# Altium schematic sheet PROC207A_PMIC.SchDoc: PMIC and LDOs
size 431 x 279 mm; Date: Not shown in title block; ApprovedBy: Not shown in title block; CheckedBy: Not shown in title block; Author: Not shown in title block; CompanyName: Not shown in title block; DrawnBy: Mistral; Engineer: Not shown in title block; Organization: Not shown in title block; Address1: Not shown in title block; Address2: Not shown in title block; Address3: Not shown in title block; Address4: Not shown in title block; DocumentNumber: 16; Revision: Use project parameter SCH_Rev; SheetNumber: 5; SheetTotal: 18; PageSetup: Record=PageOptions¦CenterHorizontal=True¦CenterVertical=True¦PrintScale=1.00¦XCorrection=1.00¦YCorrection=1.00¦PrintKind=0¦BorderSize=5000000¦LeftOffset=0¦BottomOffset=0¦Orientation=2¦PaperLength=1000¦PaperWidth=1000¦Scale=100¦PaperSource=15¦PrintQuality=600¦MediaType=1¦DitherType=10¦PaperKind=Letter¦PrintScaleMode=1
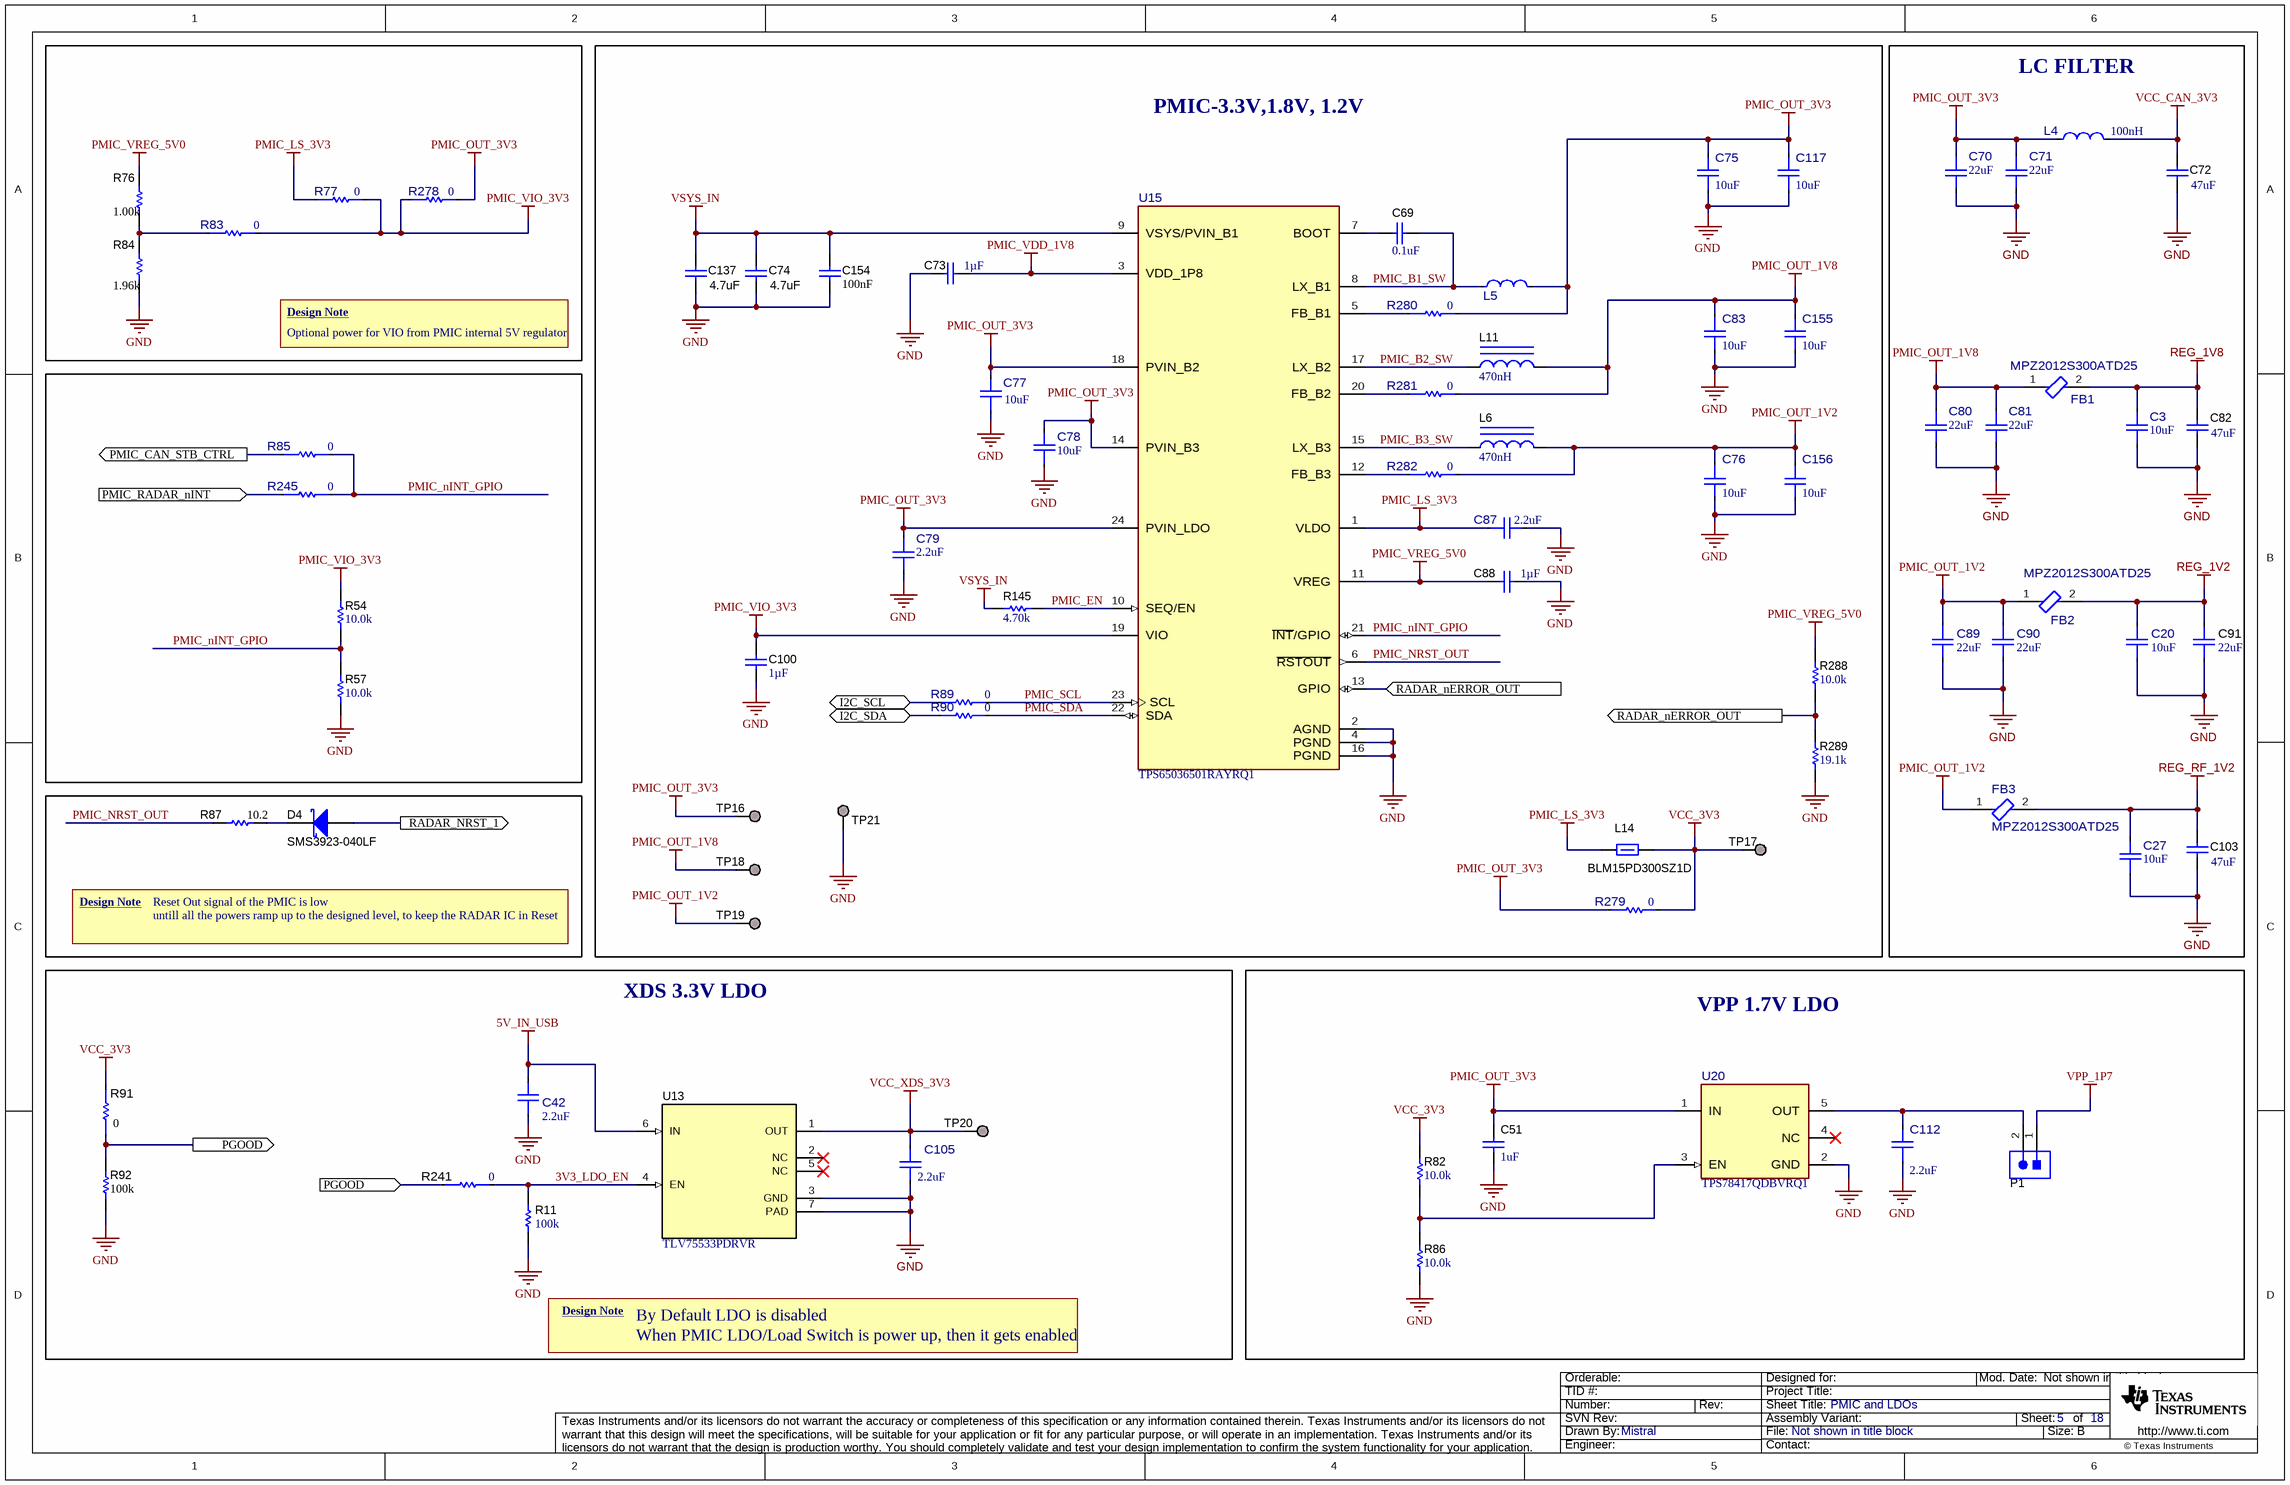
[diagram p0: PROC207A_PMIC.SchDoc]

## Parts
C3  ValueDisplayed: 10uF  [FP-CGA4J3X7S1A106K125AE_0805-MFG]  (hidden comment: CGA4J3X7S1A106K125AE)
C20  ValueDisplayed: 10uF  [FP-CGA4J3X7S1A106K125AE_0805-MFG]  (hidden comment: CGA4J3X7S1A106K125AE)
C27  ValueDisplayed: 10uF  [FP-CGA4J3X7S1A106K125AE_0805-MFG]  (hidden comment: CGA4J3X7S1A106K125AE)
C42  ValueDisplayed: 2.2uF  [FP-GRT155C71A225KE13D_0402-MFG]  (hidden comment: GRT155C71A225KE13D)
C51  ValueDisplayed: 1uF  [0402_070]  (hidden comment: GCM155C71A105KE38D)
C69  ValueDisplayed: 0.1uF  [0402]  (hidden comment: GCM155R71H104KE02D)
C70  ValueDisplayed: 22uF  [FP-GRM31CR70J226ME19K_1206-MFG]  (hidden comment: GRM31CR70J226ME19K)
C71  ValueDisplayed: 22uF  [FP-GRM31CR70J226ME19K_1206-MFG]  (hidden comment: GRM31CR70J226ME19K)
C72  ValueDisplayed: 47uF  [1206_180]  (hidden comment: GRM31CR60J476ME19L)
C73  Cap_F: 1µF  [0603]  (hidden comment: CL10B105KA8NNNC)
C74  ValueDisplayed: 4.7uF  [1206_180L]  (hidden comment: C3216X7R1H475K160AC)
C75  ValueDisplayed: 10uF  [FP-CGA4J3X7S1A106K125AE_0805-MFG]  (hidden comment: CGA4J3X7S1A106K125AE)
C76  ValueDisplayed: 10uF  [FP-CGA4J3X7S1A106K125AE_0805-MFG]  (hidden comment: CGA4J3X7S1A106K125AE)
C77  ValueDisplayed: 10uF  [FP-CGA4J3X7S1A106K125AE_0805-MFG]  (hidden comment: CGA4J3X7S1A106K125AE)
C78  ValueDisplayed: 10uF  [FP-CGA4J3X7S1A106K125AE_0805-MFG]  (hidden comment: CGA4J3X7S1A106K125AE)
C79  ValueDisplayed: 2.2uF  [FP-GRT155C71A225KE13D_0402-MFG]  (hidden comment: GRT155C71A225KE13D)
C80  ValueDisplayed: 22uF  [FP-GRM31CR70J226ME19K_1206-MFG]  (hidden comment: GRM31CR70J226ME19K)
C81  ValueDisplayed: 22uF  [FP-GRM31CR70J226ME19K_1206-MFG]  (hidden comment: GRM31CR70J226ME19K)
C82  ValueDisplayed: 47uF  [1206_180]  (hidden comment: GRM31CR60J476ME19L)
C83  ValueDisplayed: 10uF  [FP-CGA4J3X7S1A106K125AE_0805-MFG]  (hidden comment: CGA4J3X7S1A106K125AE)
C87  ValueDisplayed: 2.2uF  [FP-GRT155C71A225KE13D_0402-MFG]  (hidden comment: GRT155C71A225KE13D)
C88  Cap_F: 1µF  [0603]  (hidden comment: CL10B105KA8NNNC)
C89  ValueDisplayed: 22uF  [FP-GRM31CR70J226ME19K_1206-MFG]  (hidden comment: GRM31CR70J226ME19K)
C90  ValueDisplayed: 22uF  [FP-GRM31CR70J226ME19K_1206-MFG]  (hidden comment: GRM31CR70J226ME19K)
C91  ValueDisplayed: 22uF  [FP-GRM31CR70J226ME19K_1206-MFG]  (hidden comment: GRM31CR70J226ME19K)
C100  Cap_F: 1µF  [0603]  (hidden comment: CL10B105KA8NNNC)
C103  ValueDisplayed: 47uF  [1206_180]  (hidden comment: GRM31CR60J476ME19L)
C105  ValueDisplayed: 2.2uF  [FP-GRT155C71A225KE13D_0402-MFG]  (hidden comment: GRT155C71A225KE13D)
C112  ValueDisplayed: 2.2uF  [FP-GRT155C71A225KE13D_0402-MFG]  (hidden comment: GRT155C71A225KE13D)
C117  ValueDisplayed: 10uF  [FP-CGA4J3X7S1A106K125AE_0805-MFG]  (hidden comment: CGA4J3X7S1A106K125AE)
C137  ValueDisplayed: 4.7uF  [1206_180L]  (hidden comment: C3216X7R1H475K160AC)
C154  Cap_F: 100nF  [0402]  (hidden comment: GCM155R71H104KE02D)
C155  ValueDisplayed: 10uF  [FP-CGA4J3X7S1A106K125AE_0805-MFG]  (hidden comment: CGA4J3X7S1A106K125AE)
C156  ValueDisplayed: 10uF  [FP-CGA4J3X7S1A106K125AE_0805-MFG]  (hidden comment: CGA4J3X7S1A106K125AE)
D4  SMS3923-040LF  [SOD-882]
FB1  MPZ2012S300ATD25  [FP-MPZ2012S300ATD25_0805-MFG]
FB2  MPZ2012S300ATD25  [FP-MPZ2012S300ATD25_0805-MFG]
FB3  MPZ2012S300ATD25  [FP-MPZ2012S300ATD25_0805-MFG]
L4  Ind_H: 100nH  [FP-LQM2MPZR10MJHL_0806 (2016)-MFG]  (hidden comment: LQM2MPZR10MJHL)
L5  TFM252012ALVA1R5MTAA  [FP-TFM252012ALVA1R5MTAA_1008-MFG]  (value not drawn)
L6  ValueDisplayed: 470nH  [TFM201610ALMA]  (hidden comment: TFM201610ALMAR47MTAA)
L11  ValueDisplayed: 470nH  [TFM201610ALMA]  (hidden comment: TFM201610ALMAR47MTAA)
L14  BLM15PD300SZ1D  [0402L]
P1  TSW-102-07-G-S  [TSW-102-07-G-S]  (value not drawn)
R11  ValueDisplayed: 100k  [0402]  (hidden comment: CRCW0402100KFKED)
R54  ValueDisplayed: 10.0k  [0402L]  (hidden comment: CRCW040210K0FKED)
R57  ValueDisplayed: 10.0k  [0402L]  (hidden comment: CRCW040210K0FKED)
R76  ValueDisplayed: 1.00k  [0402]  (hidden comment: ERJ-2RKF1001X)
R77  value 0  [FP-ERJ-2GE0R00X_0402-MFG]  (hidden comment: ERJ-2GE0R00X)
R82  ValueDisplayed: 10.0k  [0402L]  (hidden comment: CRCW040210K0FKED)
R83  value 0  [FP-ERJ-2GE0R00X_0402-MFG]  (hidden comment: ERJ-2GE0R00X)
R84  ValueDisplayed: 1.96k  [0402]  (hidden comment: CRCW04021K96FKED)
R85  value 0  [FP-ERJ-2GE0R00X_0402-MFG]  (hidden comment: ERJ-2GE0R00X)
R86  ValueDisplayed: 10.0k  [0402L]  (hidden comment: CRCW040210K0FKED)
R87  ValueDisplayed: 10.2  [0402]  (hidden comment: CRCW040210R2FKED)
R89  value 0  [FP-ERJ-2GE0R00X_0402-MFG]  (hidden comment: ERJ-2GE0R00X)
R90  value 0  [FP-ERJ-2GE0R00X_0402-MFG]  (hidden comment: ERJ-2GE0R00X)
R91  value 0  [FP-ERJ-2GE0R00X_0402-MFG]  (hidden comment: ERJ-2GE0R00X)
R92  ValueDisplayed: 100k  [0402]  (hidden comment: CRCW0402100KFKED)
R145  value 4.70k  [0402]  (hidden comment: RC0402FR-074K7L)
R241  value 0  [FP-ERJ-2GE0R00X_0402-MFG]  (hidden comment: ERJ-2GE0R00X)
R245  value 0  [FP-ERJ-2GE0R00X_0402-MFG]  (hidden comment: ERJ-2GE0R00X)
R278  value 0  [FP-ERJ-2GE0R00X_0402-MFG]  (hidden comment: ERJ-2GE0R00X)
R279  value 0  [FP-ERJ-2GE0R00X_0402-MFG]  (hidden comment: ERJ-2GE0R00X)
R280  value 0  [FP-ERJ-2GE0R00X_0402-MFG]  (hidden comment: ERJ-2GE0R00X)
R281  value 0  [FP-ERJ-2GE0R00X_0402-MFG]  (hidden comment: ERJ-2GE0R00X)
R282  value 0  [FP-ERJ-2GE0R00X_0402-MFG]  (hidden comment: ERJ-2GE0R00X)
R288  ValueDisplayed: 10.0k  [0402L]  (hidden comment: CRCW040210K0FKED)
R289  ValueDisplayed: 19.1k  [0402]  (hidden comment: CRCW040219K1FKED)
TP16  TESTPOINT  [TP_25MIL-SMT]  (value not drawn)  (no BOM)
TP17  TESTPOINT  [TP_25MIL-SMT]  (value not drawn)  (no BOM)
TP18  TESTPOINT  [TP_25MIL-SMT]  (value not drawn)  (no BOM)
TP19  TESTPOINT  [TP_25MIL-SMT]  (value not drawn)  (no BOM)
TP20  TESTPOINT  [TP_25MIL-SMT]  (value not drawn)  (no BOM)
TP21  TESTPOINT  [TP_VIA_060RND040]  (value not drawn)  (no BOM)
U13  TLV75533PDRVR  [DRV0006A]
U15  TPS65036501RAYRQ1  [RAY0024B-MFG]
U20  TPS78417QDBVRQ1  [DBV0005A-MFG]

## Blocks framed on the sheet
PMIC-3.3V,1.8V, 1.2V: C69 C73-C79 C83 C87 C88 C100 C117 C137 C154-C156 L5 L6 L11 L14 R89 R90 R145 R279-R282 R288 R289 TP16-TP19 TP21 U15
LC FILTER: C3 C20 C27 C70-C72 C80-C82 C89-C91 C103 FB1-FB3 L4
VPP 1.7V LDO: C51 C112 P1 R82 R86 U20

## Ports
I2C_SCL (bidir), I2C_SDA (bidir), PGOOD (in), PGOOD (out), PMIC_CAN_STB_CTRL (out), PMIC_RADAR_nINT (in), RADAR_nERROR_OUT (in), RADAR_nERROR_OUT (out), RADAR_NRST_1 (out)

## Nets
5V_IN_USB: C42.2 U13.6(IN)
GND: C3.1 C20.1 C27.1 C42.1 C51.2 C70.2 C71.2 C72.1 C73.2 C74.2 C75.1 C76.2 C77.1 C78.1 C79.2 C80.2 C81.2 C82.1 C83.2 C87.2 C88.1 C89.2 C90.2 C91.1 C100.2 C103.1 C105.2 C112.1 C117.1 C137.2 C154.1 C155.1 C156.1 R11.1 R57.1 R84.1 R86.1 R92.1 R289.1 TP21.1 U13.3(GND) U13.7(PAD) U15.2(AGND) U15.4(PGND) U15.16(PGND) U20.2(GND)
PMIC_LS_3V3: C87.1 L14.1 R77.1 U15.1(VLDO)
PMIC_OUT_1V2: C76.1 C89.1 C90.1 C156.2 FB2.1 FB3.1 L6.2 R282.2 TP19.1
PMIC_OUT_1V8: C80.1 C81.1 C83.1 C155.2 FB1.1 L11.2 R281.2 TP18.1
PMIC_OUT_3V3: C51.1 C70.1 C71.1 C75.2 C77.2 C78.2 C79.1 C117.2 L4.1 L5.2 R278.2 R279.1 R280.2 TP16.1 U15.14(PVIN_B3) U15.18(PVIN_B2) U15.24(PVIN_LDO) U20.1(IN)
PMIC_VDD_1V8: C73.1 U15.3(VDD_1P8)
PMIC_VIO_3V3: C100.1 R54.2 R77.2 R83.2 R278.1 U15.19(VIO)
PMIC_VREG_5V0: C88.2 R76.1 R288.2 U15.11(VREG)
REG_1V2: C20.2 C91.2 FB2.2
REG_1V8: C3.2 C82.2 FB1.2
REG_RF_1V2: C27.2 C103.2 FB3.2
VCC_3V3: L14.2 R82.2 R91.2 R279.2 TP17.1
VCC_CAN_3V3: C72.2 L4.2
VCC_XDS_3V3: C105.1 TP20.1 U13.1(OUT)
VPP_1P7: P1.1
VSYS_IN: C74.1 C137.1 C154.2 R145.2 U15.9(VSYS/PVIN_B1)
3V3_LDO_EN: R11.2 R241.2 U13.4(EN)
I2C_SCL: R89.1 ; port I2C_SCL
I2C_SDA: R90.1 ; port I2C_SDA
PGOOD: R91.1 R92.2 R241.1 ; port PGOOD
PMIC_B1_SW: C69.2 L5.1 U15.8(LX_B1)
PMIC_B2_SW: L11.1 U15.17(LX_B2)
PMIC_B3_SW: L6.1 U15.15(LX_B3)
PMIC_CAN_STB_CTRL: R85.1 ; port PMIC_CAN_STB_CTRL
PMIC_EN: R145.1 U15.10(SEQ/EN)
PMIC_nINT_GPIO: R54.1 R57.2 R85.2 R245.2 U15.21(~{INT}/GPIO)
PMIC_NRST_OUT: R87.1 U15.6(~{RSTOUT})
PMIC_RADAR_nINT: R245.1 ; port PMIC_RADAR_nINT
PMIC_SCL: R89.2 U15.23(SCL)
PMIC_SDA: R90.2 U15.22(SDA)
RADAR_nERROR_OUT: R288.1 R289.2 U15.13(GPIO) ; port RADAR_nERROR_OUT
RADAR_NRST_1: D4.2(A) ; port RADAR_NRST_1
NetC69_1: C69.1 U15.7(BOOT)
NetC112_2: C112.2 P1.2 U20.5(OUT)
NetD4_1: D4.1(K) R87.2
NetR76_2: R76.2 R83.1 R84.2
NetR82_1: R82.1 R86.2 U20.3(EN)
NetR280_1: R280.1 U15.5(FB_B1)
NetR281_1: R281.1 U15.20(FB_B2)
NetR282_1: R282.1 U15.12(FB_B3)

Not connected (* = marked no-connect by the designer): U13 2(NC)* 5(NC)*; U20 4(NC)*

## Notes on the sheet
- Design Note
- Optional power for VIO from PMIC internal 5V regulator
- Reset Out signal of the PMIC is low
- untill all the powers ramp up to the designed level, to keep the RADAR IC in Reset
- XDS 3.3V LDO
- By Default LDO is disabled
- When PMIC LDO/Load Switch is power up, then it gets enabled

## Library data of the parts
C3 C20 C27 C75-C78 C83 C117 C155 C156 = CMP-0089543-1: 10µF ±10% 10V Ceramic Capacitor X7S 0805 (2012 Metric); Manufacturer: TDK; TempCo: 22%; SizeZ_mm: 1.5mm; AEC Qualified: Yes; AEC Grade: Grade 1
C42 C79 C87 C105 = CMP-0094968-1: Multi-Layer Ceramic Capacitor 2.2uF 10V X7S ±10% 0402 Paper T/R; Manufacturer: Murata; TempCo: 22%; Value: 2.2µF; SizeZ_mm: 0.7mm; AEC Qualified: Yes; AEC Grade: Grade 1
C51 = CMP-0006349-2: CAP, CERM, 1 uF, 10 V, +/- 10%, X7S, AEC-Q200 Grade 1, 0402; Manufacturer: MuRata; Polarized: N; Value: 1uF; U/M: EA; Cap_F: 1µF; Value1: Unknown; VDC_V: 10V; TaMin_C: -55°C; TaMax_C: 125°C; Cap_Case: 0402; SizeArea_mm2: 0.5; SizeAreaWB_mm2: 3; SizeX_mm: 1; SizeZ_mm: 0.7; AEC Category: Q200; AEC Qualified: Y
C69 = CMP-0006356-2: CAP, CERM, 0.1 uF, 50 V, +/- 10%, X7R, AEC-Q200 Grade 1, 0402; Manufacturer: MuRata; TaMin_C: -55°C; Polarized: N; SizeAreaWB_mm2: 3; Value1: Unknown; U/M: EA; Value: 0.1uF; TaMax_C: 125°C; SizeZ_mm: 0.6; SizeX_mm: 1; SizeY_mm: 0.5; Value2: 50V; AEC Qualified: Y; Cap_F: 100nF; AEC Category: Q200
C70 C71 C80 C81 C89 C90 = CMP-0092150-1: Chip Multilayer Ceramic Capacitors for General Purpose, 1206, 22uF, X7R, 15%, 20%, 6.3V; Manufacturer: Murata; Value: 22µF; SizeZ_mm: 1.8mm; AEC Qualified: No
C72 C82 C103 = CMP-0008940-2: CAP, CERM, 47 uF, 6.3 V, +/- 20%, X5R, 1206; Manufacturer: MuRata; TaMin_C: -55°C; ESR_ohm: 3m; Polarized: N; SizeAreaWB_mm2: 10.92; Value1: 0.003 ohm; U/M: EA; Value: 47uF; TaMax_C: 85°C; SizeZ_mm: 1.8; SizeX_mm: 3.2; SizeY_mm: 1.6; Cap_Case: 1206; Value2: 6.3V; SizeArea_mm2: 5.12; Cap_F: 47µF; AEC Category: Q200
C73 C88 C100 = CMP-0086540-3: CAP, 1uF, 25V, ±10%, X7R, 0603; Manufacturer: Samsung; TempCo: 15%; SizeZ_mm: 0.9mm; AEC Qualified: No; Symbol Name: SYM-CL10B105KA8NNNC
C74 C137 = CMP-0008702-2: CAP, CERM, 4.7 uF, 50 V, +/- 10%, X7R, 1206; Manufacturer: TDK; TaMin_C: -55°C; ESR_ohm: 3.158m; Polarized: N; SizeAreaWB_mm2: 10.92; Value1: 0.003158 ohm; U/M: EA; Value: 4.7uF; TaMax_C: 125°C; SizeZ_mm: 1.8; SizeX_mm: 3.2; SizeY_mm: 1.6; Cap_Case: 1206_180; Value2: 50V; SizeArea_mm2: 5.12; Cap_F: 4.7µF; IRMS_A: 4.08379A; AEC Category: Q200
C91 = CMP-0092150-1: Chip Multilayer Ceramic Capacitors for General Purpose, 1206, 22uF, X7R, 15%, 20%, 6.3V; Manufacturer: Murata; SizeZ_mm: 1.8mm; AEC Qualified: No; Value: 22µF
C112 = CMP-0094968-1: Multi-Layer Ceramic Capacitor 2.2uF 10V X7S ±10% 0402 Paper T/R; Manufacturer: Murata; AEC Grade: Grade 1; Cap_F: 2.2µF; SizeZ_mm: 0.7mm; Value: 2.2µF; AEC Qualified: Yes; TempCo: 22%
C154 = CMP-0006356-2: CAP, CERM, 0.1 uF, 50 V, +/- 10%, X7R, AEC-Q200 Grade 1, 0402; Manufacturer: MuRata; AEC Qualified: Y; SizeZ_mm: 0.6; VDC_V: 50V; AEC Category: Q200; AEC Grade: 1; Polarized: N; SizeArea_mm2: 0.5; SizeAreaWB_mm2: 3; TaMax_C: 125°C; TaMin_C: -55°C; U/M: EA; Value1: Unknown; Value: 0.1uF
D4 = CMP-0078187-3: Diode, Schottky,  V, 0.01 A, SOD-882; Manufacturer: Skyworks Solutions; SizeArea_mm2: 0.6; SizeAreaWB_mm2: 3.2; Io_A: 10mA; SizeX_mm: 1; Value1: 0.01A; SizeZ_mm: 0.5; Value2: 0.34V; AEC Category: Q101; Vf_V: 340mV; TJmax_C: 150°C; AEC Qualified: N
FB1-FB3 = CMP-0091544-1: 30 Ohms @ 100MHz 1 Power Line Ferrite Bead 0805 (2012 Metric) 6A 10mOhm; Manufacturer: TDK; AEC Grade: Grade 1; Impedance At Frequency: 30Ω @ 100MHz; SizeZ_mm: 1.05mm; DCR_ohm: 10m; AEC Qualified: Yes
L4 = CMP-0095018-1: 100nH Shielded Multilayer Inductor 4A 19mOhm Max 0806 (2016 Metric); Manufacturer: Murata; Tolerance_%: 20%; Self Resonant Frequency: 200MHz; Test Frequency: 1MHz; Irms: 4000mA; Shrouded: true; SizeZ_mm: 1.2mm; Value: 0.1uH; AEC Grade: Grade 1; DCR_ohm: 0.019; Material: Ferrite; AEC Qualified: Yes
L5 = CMP-0121156-1: 1.5 µH Shielded Thin Film Inductor 3.1 A 60mOhm Max 1008 (2520 Metric); Manufacturer: TDK; AEC Grade: Grade 0; AEC Qualified: Yes; DCR_ohm: 60m; Ind_H: 1.5µH; Irms: 3.3A; Material: Metal; SizeZ_mm: 1.2mm; Value: 1.5uH; Shrouded: true; Test Frequency: 1MHz; Tolerance_%: 20%
L6 L11 = CMP-0081095-1: Inductor, Shielded, Metal Composite, 470 nH, 3.9 A, 0.039 ohm, AEC-Q200 Grade 0, SMD; Manufacturer: TDK; Isat: 4.5A @ 30% inductance drop; Irms: 3.9A @ 40C rise; SizeAreaWB_mm2: 7.8; DCR_ohm: 39m; Value: 470nH; Imax_A: 3.9A; SizeZ_mm: 1; SizeX_mm: 2; SizeY_mm: 1.6; SizeArea_mm2: 3.2; AEC Qualified: Y; AEC Grade: 0; AEC Category: Q200
L14 = CMP-0078934-1: Inductor, Ferrite Bead, Ferrite, 2.2 A, 0.035 ohm, AEC-Q200 Grade 1, SMD; Manufacturer: MuRata; AEC Category: Q200; AEC Grade: 1; AEC Qualified: Y; DCR_ohm: 0.035; Imax_A: 2.2A; SizeArea_mm2: 0.5; SizeAreaWB_mm2: 3; SizeZ_mm: 0.6
P1 = CMP-0075405-3: Header, 100mil, 2x1, Gold, TH; Manufacturer: Samtec; Pitch_mm: 2.54; Cert_VDE: N; Gender: Male; Cert_CSA: Y; Voltage_V: 550V; Green_REACh: Passed; Current_A: 6.3A; Green_Lifecycle: Active; Row_Count: 1
R11 R92 = CMP-0025950-3: RES, 100 k, 1%, 0.063 W, AEC-Q200 Grade 0, 0402; Manufacturer: Vishay-Dale; Power_W: 63mW; TempCo: 100 ppm/C; Value: 100k; EIA_Code: E96; SizeX_mm: 1; SizeY_mm: 0.5; SizeZ_mm: 0.6; Value2: 0.063W; AEC Qualified: Y; VDC_V: 50V; AEC Category: Q200; AEC Grade: 0
R54 R57 R82 R86 R288 = CMP-0025958-3: RES, 10.0 k, 1%, 0.063 W, AEC-Q200 Grade 0, 0402; Manufacturer: Vishay-Dale; Power_W: 63mW; TempCo: 100 ppm/C; Value_Code: 10k0; Value: 10.0k; EIA_Code: E96; Res_ohm: 10k; SizeX_mm: 1; SizeY_mm: 0.5; SizeZ_mm: 0.6; Value2: 0.063W; AEC Qualified: Y; VDC_V: 50V; AEC Category: Q200; AEC Grade: 0
R76 = CMP-0026657-1: RES, 1.00 k, 1%, 0.1 W, 0402; Manufacturer: Panasonic; Power_W: 100mW; TempCo: 100 ppm/C; Value_Code: 1k00; U/M: EA; Value: 1.00k; EIA_Code: E96; Res_ohm: 1k; SizeX_mm: 1; SizeY_mm: 0.5; SizeZ_mm: 0.6; Value2: 0.1W; VDC_V: 50V; AEC Category: Q200
R77 R83 R278-R282 = CMP-0002710-1: 0 Ohms Jumper Chip Resistor 0402 (1005 Metric) Automotive AEC-Q200 Thick Film; Manufacturer: Panasonic; AEC Grade: Grade 0; AEC Qualified: Yes; SizeZ_mm: 0.4mm; Power: 100mW
R84 = CMP-0026099-2: RES, 1.96 k, 1%, 0.063 W, AEC-Q200 Grade 0, 0402; Manufacturer: Vishay-Dale; Power_W: 63mW; TempCo: 100 ppm/C; Value_Code: 1k96; Value: 1.96k; EIA_Code: E96; SizeX_mm: 1; SizeY_mm: 0.5; SizeZ_mm: 0.6; Value2: 0.063W; AEC Qualified: Y; VDC_V: 50V; AEC Category: Q200; AEC Grade: 0
R85 R89-R91 R241 R245 = CMP-0002710-1: 0 Ohms Jumper Chip Resistor 0402 (1005 Metric) Automotive AEC-Q200 Thick Film; Manufacturer: Panasonic; SizeZ_mm: 0.4mm; AEC Qualified: Yes; AEC Grade: Grade 0; Power: 100mW
R87 = CMP-0025964-3: RES, 10.2, 1%, 0.063 W, AEC-Q200 Grade 0, 0402; Manufacturer: Vishay-Dale; Power_W: 63mW; TempCo: 100 ppm/C; Value_Code: 10R2; Value: 10.2; EIA_Code: E96; SizeX_mm: 1; SizeY_mm: 0.5; SizeZ_mm: 0.6; Value2: 0.063W; AEC Qualified: Y; VDC_V: 50V; AEC Category: Q200; AEC Grade: 0
R145 = CMP-0026739-1: RES, 4.70 k, 1%, 0.0625 W, 0402; Manufacturer: Yageo America; VDC_V: 50V; AEC Qualified: N; SizeZ_mm: 0.6; TempCo: 100 ppm/C; AEC Category: Q200; Power_W: 62.5mW; Res_ohm: 4.7k; SizeArea_mm2: 0.5; SizeX_mm: 1; U/M: EA; Value_Code: 4k70
R289 = CMP-0026067-3: RES, 19.1 k, 1%, 0.063 W, AEC-Q200 Grade 0, 0402; Manufacturer: Vishay-Dale; Power_W: 63mW; TempCo: 100 ppm/C; Value_Code: 19k1; Value: 19.1k; EIA_Code: E96; SizeX_mm: 1; SizeY_mm: 0.5; SizeZ_mm: 0.6; Value2: 0.063W; AEC Qualified: Y; VDC_V: 50V; AEC Category: Q200; AEC Grade: 0
TP16-TP21 = CMP-0078143-3: TEST POINT.  No entry in BOM.
U13 = CMP-0013427-7: 500mA LDO, DRV0006A (WSON-6); Manufacturer: Texas Instruments; SizeX_mm: 2; CompType: IC; SizeZ_mm: 0.8; SizeArea_mm2: 4; SizeAreaWB_mm2: 9; U/M: EA
U15 = CMP-0123008-1: Automotive Camera, Radar and MCU PMIC; Manufacturer: Texas Instruments; SizeZ_mm: 1mm; AEC Qualified: No; Max Supply Voltage: 35V; Min Supply Voltage: 4V; Number Of Outputs: 4; Output Voltage: 3-5.5V; Standoff Height: 0mm; TaMax_C: +125°C; TaMin_C: -40°C
U20 = CMP-0092338-1: Linear Voltage Regulator IC Positive Fixed Output 300mA SOT-23-5; Manufacturer: Texas Instruments; TaMin_C: -40°C; Output Voltage: 1.7V; Standoff Height: 0mm; SizeZ_mm: 1.45mm; TaMax_C: +125°C; Accuracy Percentage: 0.5%; AEC Grade: Grade 1; Number Of Outputs: 1; AEC Qualified: Yes; Max Supply Voltage: 6V; Dropout Voltage: 900mV; Nominal Supply Current: 0.033mA; Min Supply Voltage: 1.65V; TJmax_C: +150°C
